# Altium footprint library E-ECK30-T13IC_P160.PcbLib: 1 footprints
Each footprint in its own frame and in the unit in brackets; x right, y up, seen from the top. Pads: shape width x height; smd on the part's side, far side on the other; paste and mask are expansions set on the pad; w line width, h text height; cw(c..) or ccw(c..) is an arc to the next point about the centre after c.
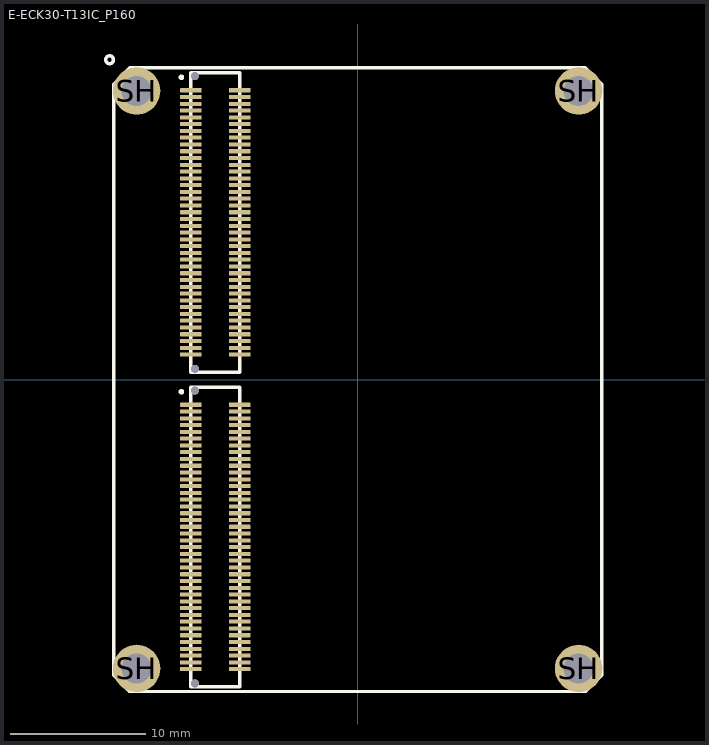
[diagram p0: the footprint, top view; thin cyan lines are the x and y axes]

## E-ECK30-T13IC_P160 [mm]
pads (168):
  rrect25% 1.6x0.3 smd: J1-1(-12.3,21.35) J1-2(-8.7,21.35) J1-3(-12.3,20.85) J1-4(-8.7,20.85) J1-5(-12.3,20.35) J1-6(-8.7,20.35) J1-7(-12.3,19.85) J1-8(-8.7,19.85) J1-9(-12.3,19.35) J1-10(-8.7,19.35) J1-11(-12.3,18.85) J1-12(-8.7,18.85) J1-13(-12.3,18.35) J1-14(-8.7,18.35) J1-15(-12.3,17.85) J1-16(-8.7,17.85) J1-17(-12.3,17.35) J1-18(-8.7,17.35) J1-19(-12.3,16.85) J1-20(-8.7,16.85) J1-21(-12.3,16.35) J1-22(-8.7,16.35) J1-23(-12.3,15.85) J1-24(-8.7,15.85) J1-25(-12.3,15.35) J1-26(-8.7,15.35) J1-27(-12.3,14.85) J1-28(-8.7,14.85) J1-29(-12.3,14.35) J1-30(-8.7,14.35) J1-31(-12.3,13.85) J1-32(-8.7,13.85) J1-33(-12.3,13.35) J1-34(-8.7,13.35) J1-35(-12.3,12.85) J1-36(-8.7,12.85) J1-37(-12.3,12.35) J1-38(-8.7,12.35) J1-39(-12.3,11.85) J1-40(-8.7,11.85) J1-41(-12.3,11.35) J1-42(-8.7,11.35) J1-43(-12.3,10.85) J1-44(-8.7,10.85) J1-45(-12.3,10.35) J1-46(-8.7,10.35) J1-47(-12.3,9.85) J1-48(-8.7,9.85) J1-49(-12.3,9.35) J1-50(-8.7,9.35) J1-51(-12.3,8.85) J1-52(-8.7,8.85) J1-53(-12.3,8.35) J1-54(-8.7,8.35) J1-55(-12.3,7.85) J1-56(-8.7,7.85) J1-57(-12.3,7.35) J1-58(-8.7,7.35) J1-59(-12.3,6.85) J1-60(-8.7,6.85) J1-61(-12.3,6.35) J1-62(-8.7,6.35) J1-63(-12.3,5.85) J1-64(-8.7,5.85) J1-65(-12.3,5.35) J1-66(-8.7,5.35) J1-67(-12.3,4.85) J1-68(-8.7,4.85) J1-69(-12.3,4.35) J1-70(-8.7,4.35) J1-71(-12.3,3.85) J1-72(-8.7,3.85) J1-73(-12.3,3.35) J1-74(-8.7,3.35) J1-75(-12.3,2.85) J1-76(-8.7,2.85) J1-77(-12.3,2.35) J1-78(-8.7,2.35) J1-79(-12.3,1.85) J1-80(-8.7,1.85) J2-1(-12.3,-1.85) J2-2(-8.7,-1.85) J2-3(-12.3,-2.35) J2-4(-8.7,-2.35) J2-5(-12.3,-2.85) J2-6(-8.7,-2.85) J2-7(-12.3,-3.35) J2-8(-8.7,-3.35) J2-9(-12.3,-3.85) J2-10(-8.7,-3.85) J2-11(-12.3,-4.35) J2-12(-8.7,-4.35) J2-13(-12.3,-4.85) J2-14(-8.7,-4.85) J2-15(-12.3,-5.35) J2-16(-8.7,-5.35) J2-17(-12.3,-5.85) J2-18(-8.7,-5.85) J2-19(-12.3,-6.35) J2-20(-8.7,-6.35) J2-21(-12.3,-6.85) J2-22(-8.7,-6.85) J2-23(-12.3,-7.35) J2-24(-8.7,-7.35) J2-25(-12.3,-7.85) J2-26(-8.7,-7.85) J2-27(-12.3,-8.35) J2-28(-8.7,-8.35) J2-29(-12.3,-8.85) J2-30(-8.7,-8.85) J2-31(-12.3,-9.35) J2-32(-8.7,-9.35) J2-33(-12.3,-9.85) J2-34(-8.7,-9.85) J2-35(-12.3,-10.35) J2-36(-8.7,-10.35) J2-37(-12.3,-10.85) J2-38(-8.7,-10.85) J2-39(-12.3,-11.35) J2-40(-8.7,-11.35) J2-41(-12.3,-11.85) J2-42(-8.7,-11.85) J2-43(-12.3,-12.35) J2-44(-8.7,-12.35) J2-45(-12.3,-12.85) J2-46(-8.7,-12.85) J2-47(-12.3,-13.35) J2-48(-8.7,-13.35) J2-49(-12.3,-13.85) J2-50(-8.7,-13.85) J2-51(-12.3,-14.35) J2-52(-8.7,-14.35) J2-53(-12.3,-14.85) J2-54(-8.7,-14.85) J2-55(-12.3,-15.35) J2-56(-8.7,-15.35) J2-57(-12.3,-15.85) J2-58(-8.7,-15.85) J2-59(-12.3,-16.35) J2-60(-8.7,-16.35) J2-61(-12.3,-16.85) J2-62(-8.7,-16.85) J2-63(-12.3,-17.35) J2-64(-8.7,-17.35) J2-65(-12.3,-17.85) J2-66(-8.7,-17.85) J2-67(-12.3,-18.35) J2-68(-8.7,-18.35) J2-69(-12.3,-18.85) J2-70(-8.7,-18.85) J2-71(-12.3,-19.35) J2-72(-8.7,-19.35) J2-73(-12.3,-19.85) J2-74(-8.7,-19.85) J2-75(-12.3,-20.35) J2-76(-8.7,-20.35) J2-77(-12.3,-20.85) J2-78(-8.7,-20.85) J2-79(-12.3,-21.35) J2-80(-8.7,-21.35)
  round 3.5 hole 2.2: SH(-16.3,-21.3) SH(-16.3,21.3) SH(16.3,-21.3) SH(16.3,21.3)
  round 0.6 hole 0.6: Un1(-12,22.4) Un2(-12,0.8) Un3(-12,-0.8) Un4(-12,-22.4)
F.SilkS:
  circle w0.254: c-18.3,23.6 r0.288
  circle w0.254: c-13,22.302 r0.08
  circle w0.254: c-13,-0.898 r0.08
  lines w0.254: -18,-21.8 -18,21.8 -16.8,23 16.8,23 18,21.8 18,-21.8 16.8,-23 -16.8,-23 -18,-21.8 ; -12.3,-22.65 -12.3,-0.55 -8.7,-0.55 -8.7,-22.65 -12.3,-22.65 ; -12.3,0.55 -12.3,22.65 -8.7,22.65 -8.7,0.55 -12.3,0.55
